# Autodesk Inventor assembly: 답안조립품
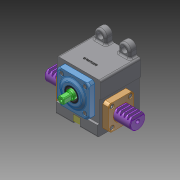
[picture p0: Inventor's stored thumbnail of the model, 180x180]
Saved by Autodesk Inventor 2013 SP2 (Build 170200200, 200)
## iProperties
Created: 2024-11
Part Number: 답안조립품
Document SubType Name: Assembly
Designer: a
Author: a
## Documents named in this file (10)
- C:\Users\a\Desktop\741104V1012\답안조립품.iam
- C:\Users\a\Desktop\741104V1012\본체.ipt
- C:\Users\a\Desktop\741104V1012\깊음 홈 볼 베어링 6202.ipt
- C:\Users\a\Desktop\741104V1012\피니언 축.ipt
- C:\Users\a\Desktop\741104V1012\커버.ipt
- C:\Users\a\Desktop\741104V1012\오일 실 15 25 4.ipt
- C:\Users\a\Desktop\741104V1012\육각 소켓 머리 볼트 M4x10.ipt
- C:\Users\a\Desktop\741104V1012\수지 부시.ipt
- C:\Users\a\Desktop\741104V1012\래크.ipt
- C:\Users\a\Desktop\741104V1012\스톱퍼.ipt
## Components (1 placed, 1 different names)
1. 피니언 축:1
